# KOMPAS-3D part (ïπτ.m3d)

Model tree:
1. Эскиз:1
2. Операция выдавливания:1
     Расстояние 1 = 250
3. Эскиз:3
4. Вырезать элемент выдавливания:1  (labels: Д16  ГОСТ 4784-97)
     Расстояние 1 = 15

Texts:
  Д16  ГОСТ 4784-97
